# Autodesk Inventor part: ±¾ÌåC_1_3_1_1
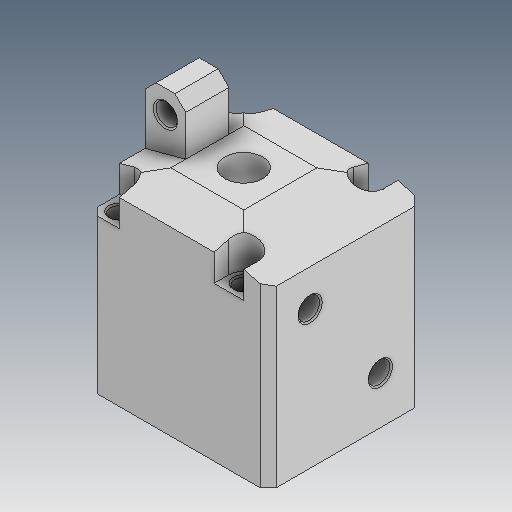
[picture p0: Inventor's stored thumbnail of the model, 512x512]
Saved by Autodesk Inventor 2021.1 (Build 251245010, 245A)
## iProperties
Created: 2019-04
Part Number: ±¾ÌåC_1_3_1_1
Material: Ogólny
Document SubType Name: Modeling
Designer: user
Density: 1 g/cm^3
Appearance: Domyślna
Author: user
Revision Number: ÈÎºÎ
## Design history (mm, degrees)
feature "ÊäÈë1"
node "Bryła1"
